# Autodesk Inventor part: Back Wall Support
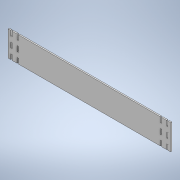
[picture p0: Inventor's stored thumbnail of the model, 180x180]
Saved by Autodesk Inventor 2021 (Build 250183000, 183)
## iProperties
Created: 2026-10
Part Number: Back Wall Support
Material: Generic
Document SubType Name: Modeling
Designer: hp
Density: 1 g/cm^3
Appearance: Default
Author: hp
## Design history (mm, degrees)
sketch "Sketch1" dims "d25" = 10, "d32" = 10
  geometry: L1 (287.975, 117.538)-(927.975, 117.538); L2 (927.975, 117.538)-(927.975, 17.538); L3 (927.975, 17.538)-(287.975, 17.538); L4 (287.975, 17.538)-(287.975, 117.538); L5 (297.975, 117.538)-(302.975, 117.538); L6 (302.975, 117.538)-(302.975, 97.538); L7 (302.975, 97.538)-(297.975, 97.538); L8 (297.975, 97.538)-(297.975, 117.538); L9 (297.975, 77.538)-(302.975, 77.538); L10 (302.975, 77.538)-(302.975, 57.538); L11 (302.975, 57.538)-(297.975, 57.538); L12 (297.975, 57.538)-(297.975, 77.538); L13 (297.975, 37.538)-(302.975, 37.538); L14 (302.975, 37.538)-(302.975, 17.538); L15 (302.975, 17.538)-(297.975, 17.538); L16 (297.975, 17.538)-(297.975, 37.538); L17 (327.975, 97.538)-(322.975, 97.538); L18 (322.975, 97.538)-(322.975, 117.538); L19 (322.975, 117.538)-(327.975, 117.538); L20 (322.975, 77.538)-(327.975, 77.538); L21 (327.975, 77.538)-(327.975, 57.538); L22 (322.975, 57.538)-(322.975, 77.538); L23 (327.975, 57.538)-(322.975, 57.538); L24 (322.975, 37.538)-(327.975, 37.538); L25 (327.975, 37.538)-(327.975, 17.538); L26 (322.975, 17.538)-(322.975, 37.538); L27 (327.975, 17.538)-(322.975, 17.538); L28 (327.975, 117.538)-(327.975, 97.538); L29 (607.975, 117.538)-(607.975, 17.538); L30 (892.975, 117.538)-(887.975, 117.538); L31 (887.975, 117.538)-(887.975, 97.538); L32 (887.975, 97.538)-(892.975, 97.538); L33 (892.975, 77.538)-(887.975, 77.538); L34 (892.975, 57.538)-(892.975, 77.538); L35 (887.975, 77.538)-(887.975, 57.538); L36 (887.975, 57.538)-(892.975, 57.538); L37 (892.975, 37.538)-(887.975, 37.538); L38 (892.975, 17.538)-(892.975, 37.538); L39 (887.975, 37.538)-(887.975, 17.538); L40 (887.975, 17.538)-(892.975, 17.538); L41 (892.975, 97.538)-(892.975, 117.538); L42 (917.975, 117.538)-(912.975, 117.538); L43 (912.975, 117.538)-(912.975, 97.538); L44 (912.975, 97.538)-(917.975, 97.538); L45 (917.975, 97.538)-(917.975, 117.538); L46 (917.975, 77.538)-(912.975, 77.538); L47 (912.975, 77.538)-(912.975, 57.538); L48 (912.975, 57.538)-(917.975, 57.538); L49 (917.975, 57.538)-(917.975, 77.538); L50 (917.975, 37.538)-(912.975, 37.538); L51 (912.975, 17.538)-(917.975, 17.538); L52 (917.975, 17.538)-(917.975, 37.538); L53 (912.975, 37.538)-(912.975, 17.538); 15 further points
  constraints: 106 end point, 24 symmetric about line, 4 parallel, 3 horizontal, 2 collinear, 2 midpoint, 2 perpendicular, 1 point on line, 1 vertical, 38 other
  dimensions: "d15" = 640 distance of L2.end L3.end; "d16" = 100 distance of L1.end L2.end; "d17" = 5 distance of L6.end L7.end; "d18" = 20 distance of L5.end L6.end; "d19" = 10 distance between parallel lines of L4 L8; "d22" = 40 distance of L5.start L9.start; "d29" = 25 distance of L7.end L17.end
extrude "Extrusion1" new body sketch "Sketch1" distance "d34" = 5; taper "d35" = 0 deg
body "Solid1"
